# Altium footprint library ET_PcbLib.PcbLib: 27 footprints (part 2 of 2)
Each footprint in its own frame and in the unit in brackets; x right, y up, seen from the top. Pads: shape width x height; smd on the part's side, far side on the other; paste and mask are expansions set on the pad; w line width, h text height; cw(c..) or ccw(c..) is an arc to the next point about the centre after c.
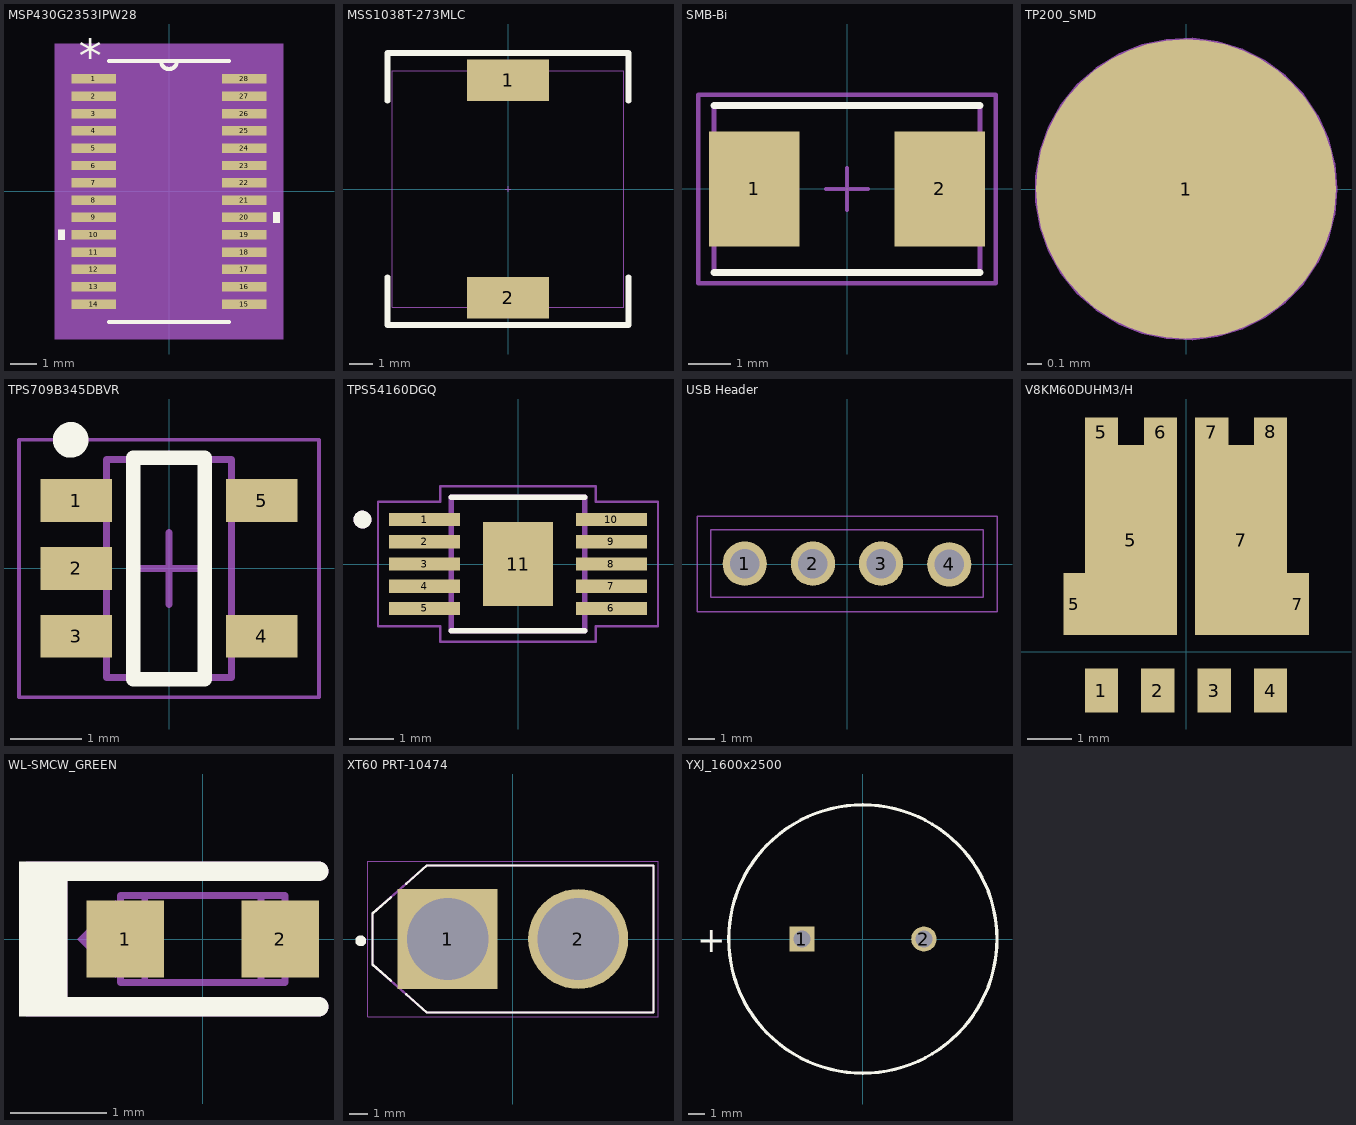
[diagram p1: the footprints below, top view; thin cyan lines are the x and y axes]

## MSP430G2353IPW28 [mil]
pads (28):
  rect 66x14 smd: 1(-111,166.34) 2(-111,140.75) 3(-111,115.16) 4(-111,89.57) 5(-111,63.98) 6(-111,38.39) 7(-111,12.8) 8(-111,-12.8) 9(-111,-38.39) 10(-111,-63.98) 11(-111,-89.57) 12(-111,-115.16) 13(-111,-140.75) 14(-111,-166.34) 15(111,-166.34) 16(111,-140.75) 17(111,-115.16) 18(111,-89.57) 19(111,-63.98) 20(111,-38.39) 21(111,-12.8) 22(111,12.8) 23(111,38.39) 24(111,63.98) 25(111,89.57) 26(111,115.16) 27(111,140.75) 28(111,166.34)
Top Overlay:
  region: -154,-56.48 -164,-56.48 -164,-71.48 -154,-71.48
  region: 154,-30.89 164,-30.89 164,-45.89 154,-45.89
  lines w6: -88.5,-193 88.5,-193 ; -88.5,193 88.5,193 ; -12,193 ccw(c0,193) 12,193
  text "*" at -133.5,175.34 h50
Mechanical 5:
  region: 169,-218 -169,-218 -169,218 169,218
Mechanical 13:
  lines w0: -12,193 ccw(c0,193) 12,193
  lines w1: -130,-172.34 -130,-160.34 -88.5,-160.34 -88.5,-172.34 -130,-172.34 ; -130,-146.75 -130,-134.75 -88.5,-134.75 -88.5,-146.75 -130,-146.75 ; -130,-121.16 -130,-109.16 -88.5,-109.16 -88.5,-121.16 -130,-121.16 ; -130,-95.57 -130,-83.57 -88.5,-83.57 -88.5,-95.57 -130,-95.57 ; -130,-69.98 -130,-57.98 -88.5,-57.98 -88.5,-69.98 -130,-69.98 ; -130,-44.39 -130,-32.39 -88.5,-32.39 -88.5,-44.39 -130,-44.39 ; -130,-18.8 -130,-6.8 -88.5,-6.8 -88.5,-18.8 -130,-18.8 ; -130,6.8 -130,18.8 -88.5,18.8 -88.5,6.8 -130,6.8 ; -130,32.39 -130,44.39 -88.5,44.39 -88.5,32.39 -130,32.39 ; -130,57.98 -130,69.98 -88.5,69.98 -88.5,57.98 -130,57.98 ; -130,83.57 -130,95.57 -88.5,95.57 -88.5,83.57 -130,83.57 ; -130,109.16 -130,121.16 -88.5,121.16 -88.5,109.16 -130,109.16 ; -130,134.75 -130,146.75 -88.5,146.75 -88.5,134.75 -130,134.75 ; -130,160.34 -130,172.34 -88.5,172.34 -88.5,160.34 -130,160.34 ; -88.5,-193 88.5,-193 88.5,193 -88.5,193 -88.5,-193 ; 88.5,-172.34 88.5,-160.34 130,-160.34 130,-172.34 88.5,-172.34 ; 88.5,-146.75 88.5,-134.75 130,-134.75 130,-146.75 88.5,-146.75 ; 88.5,-121.16 88.5,-109.16 130,-109.16 130,-121.16 88.5,-121.16 ; 88.5,-95.57 88.5,-83.57 130,-83.57 130,-95.57 88.5,-95.57 ; 88.5,-69.98 88.5,-57.98 130,-57.98 130,-69.98 88.5,-69.98 ; 88.5,-44.39 88.5,-32.39 130,-32.39 130,-44.39 88.5,-44.39 ; 88.5,-18.8 88.5,-6.8 130,-6.8 130,-18.8 88.5,-18.8 ; 88.5,6.8 88.5,18.8 130,18.8 130,6.8 88.5,6.8 ; 88.5,32.39 88.5,44.39 130,44.39 130,32.39 88.5,32.39 ; 88.5,57.98 88.5,69.98 130,69.98 130,57.98 88.5,57.98 ; 88.5,83.57 88.5,95.57 130,95.57 130,83.57 88.5,83.57 ; 88.5,109.16 88.5,121.16 130,121.16 130,109.16 88.5,109.16 ; 88.5,134.75 88.5,146.75 130,146.75 130,134.75 88.5,134.75 ; 88.5,160.34 88.5,172.34 130,172.34 130,160.34 88.5,160.34
  text "*" at -133.5,175.34 h50
Mechanical 15:
  region: 154,-203 -154,-203 -154,203 154,203
  lines w6: -154,-203 -154,203 154,203 154,-203 -154,-203
3D body "MSP430G2353IPW28.step": height 47.09, standoff 0, extent -129.99,-192.99 130.01,193
3D body: height 10, standoff 0, extent 0,0 10,10

## MSS1038T-273MLC [mil] "Coilcraft Shielded Power Inductors"
height 150
pads (2):
  rect 140x70 smd: 1(0,185) 2(0,-185)
Top Overlay:
  lines w10: -205,-150 -205,-231.5 205,-231.5 205,-150 ; -205,150 -205,231.5 205,231.5 205,150
Mechanical 13:
  lines w1: -5,0 5,0 ; 0,-5 0,5
Mechanical 14:
  lines w1: -197,-201 197,-201 197,201 -197,201 -197,-201
3D body "MSS1038.STEP": height 157.54, standoff 0.06, extent -200.79,-202.76 200.78,202.75

## SMB-Bi [mm] "Molded Diode, 2-Leads, Body 5.4x3.6mm, IPC Medium Density, based on OnSemi component dimensions"
height 2.65
pads (2):
  rect 2.159x2.743 smd: 1(-2.21,0) 2(2.21,0)
Top Overlay:
  lines w0.178: -3.175,-1.994 3.175,-1.994 ; -3.175,1.994 3.175,1.994
Mechanical 5:
  lines w0.127: -3.175,-1.994 3.175,-1.994 3.175,-1.765 3.175,1.765 3.175,1.994 -3.175,1.994 -3.175,1.765 -3.175,-1.765 -3.175,-1.994
  text ".Designator" at -2.311,-0.508 h1.02
Mechanical 15:
  lines w0.1: -0.5,0 0.5,0 ; 0,-0.5 0,0.5 ; -3.55,-2.25 -3.55,2.25 3.55,2.25 3.55,-2.25 -3.55,-2.25
3D body "SMB-Bi.stp": height 2.26, standoff 0.01, extent -2.65,-1.85 2.65,1.85

## TP200_SMD [mm] "Test Point, Single Side Land,2.00mm Land SMD"
pads (1):
  round 2.1 smd paste-10 mask-0.1: 1(0,0)
Mechanical 7:
  circle w0.02: c0,0 r1.05
Mechanical 9:
  lines w0.02: -0.5,0 0.5,0 ; 0,-0.5 0,0.5
Mechanical 11:
  text ".Designator" at -0.85,-0.15 h0.8
3D body: height 0.02, standoff 0, extent -0.992,-0.998 1,0.998

## TPS709B345DBVR [mm] "SOT23, 5-Leads, Body 2.90x2.80mm, Pitch 0.95mm, IPC Medium Density"
height 1.45
pads (5):
  rect 1x0.6 smd: 1(-1.3,0.95) 2(-1.3,0) 3(-1.3,-0.95) 4(1.3,-0.95) 5(1.3,0.95)
Top Overlay:
  circle w0.25: c-1.375,1.8 r0.125
  lines w0.2: -0.5,-1.55 -0.5,1.55 0.5,1.55 0.5,-1.55 -0.5,-1.55
Top Assembly:
  lines w0.1: -0.875,-1.525 0.875,-1.525 0.875,1.525 -0.875,1.525 -0.875,-1.525
Top Courtyard:
  lines w0.05: -2.1,-1.8 2.1,-1.8 2.1,1.8 -2.1,1.8 -2.1,-1.8
  lines w0.1: -0.5,0 0.5,0 ; 0,-0.5 0,0.5
Mechanical 11:
  text ".Designator" at -0.5,1.5 h1.5
3D body "SOT95P280X145-5N.step": height 1.45, standoff 0, extent -1.5,-1.525 1.5,1.525

## TPS54160DGQ [mm]
pads (11):
  rect 1.6x0.3 smd paste-2 mask+0: 1(-2.1,1) 2(-2.1,0.5) 3(-2.1,0) 4(-2.1,-0.5) 5(-2.1,-1) 6(2.1,-1) 7(2.1,-0.5) 8(2.1,0) 9(2.1,0.5) 10(2.1,1)
  rect 1.57x1.88 smd: 11(0,0)
Top Overlay:
  circle w0.2: c-3.5,1 r0.1
  lines w0.127: -1.5,-1.5 1.5,-1.5 ; -1.5,1.5 1.5,1.5
Top Paste:
  region: 2.875,0.875 1.325,0.875 1.325,1.125 2.875,1.125
  region: 2.875,0.375 1.325,0.375 1.325,0.625 2.875,0.625
  region: 2.875,-0.125 1.325,-0.125 1.325,0.125 2.875,0.125
  region: 2.875,-0.625 1.325,-0.625 1.325,-0.375 2.875,-0.375
  region: 2.875,-1.125 1.325,-1.125 1.325,-0.875 2.875,-0.875
  region: -1.325,-1.125 -2.875,-1.125 -2.875,-0.875 -1.325,-0.875
  region: -1.325,-0.625 -2.875,-0.625 -2.875,-0.375 -1.325,-0.375
  region: -1.325,-0.125 -2.875,-0.125 -2.875,0.125 -1.325,0.125
  region: -1.325,0.375 -2.875,0.375 -2.875,0.625 -1.325,0.625
  region: -1.325,0.875 -2.875,0.875 -2.875,1.125 -1.325,1.125
Top Solder:
  region: 2.95,0.8 1.25,0.8 1.25,1.2 2.95,1.2
  region: 2.95,0.3 1.25,0.3 1.25,0.7 2.95,0.7
  region: 2.95,-0.2 1.25,-0.2 1.25,0.2 2.95,0.2
  region: 2.95,-0.7 1.25,-0.7 1.25,-0.3 2.95,-0.3
  region: 2.95,-1.2 1.25,-1.2 1.25,-0.8 2.95,-0.8
  region: -1.25,-1.2 -2.95,-1.2 -2.95,-0.8 -1.25,-0.8
  region: -1.25,-0.7 -2.95,-0.7 -2.95,-0.3 -1.25,-0.3
  region: -1.25,-0.2 -2.95,-0.2 -2.95,0.2 -1.25,0.2
  region: -1.25,0.3 -2.95,0.3 -2.95,0.7 -1.25,0.7
  region: -1.25,0.8 -2.95,0.8 -2.95,1.2 -1.25,1.2
Mechanical 13:
  circle w0.2: c-3.5,1 r0.1
  lines w0.127: -1.5,-1.5 1.5,-1.5 1.5,1.5 -1.5,1.5 -1.5,-1.5
Mechanical 15:
  lines w0.05: -3.15,-1.4 -1.75,-1.4 -1.75,-1.75 1.75,-1.75 1.75,-1.4 3.15,-1.4 3.15,1.4 1.75,1.4 1.75,1.75 -1.75,1.75 -1.75,1.4 -3.15,1.4 -3.15,-1.4
3D body "step_temp.STEP": height 1.1, standoff 0, extent -2.45,-1.5 2.45,1.5

## USB Header [mil] "1x4 Header, Through Hole, Vertical"
height 336
pads (4):
  round 65 hole 43.3 mask+2.95: 1(-150,0.5) 2(-50,0.5) 3(50,0.5) 4(150.01,-0.5)
Mechanical 5:
  lines w1.97: -220,-70 220,-70 220,70 -220,70 -220,-70
Mechanical 7:
  lines w1.97: -199.99,-48.99 200,-48.99 200,50 -199.99,50 -199.99,-48.99
Mechanical 11:
  text ".Designator" at 230,30 h59.06
3D body "61300411121_Downlaod_STP_61300411121_rev1.stp": height 341.22, standoff -113.11, extent -200,-50 200,50

## V8KM60DUHM3/H [mm]
pads (12):
  rect 0.75x1 smd: 1(-1.905,-0.875) 2(-0.635,-0.875) 3(0.635,-0.875) 4(1.905,-0.875)
  rect 0.5x1.4 smd: 5(-2.514,1.073) 7(2.52,1.074)
  rect 0.75x0.65 smd: 5(-1.905,4.95) 6(-0.574,4.95) 7(0.577,4.95) 8(1.905,4.953)
  rect 2.08x4.28 smd: 5(-1.24,2.515) 7(1.24,2.515)

## WL-SMCW_GREEN [mm] "WURTH"
height 0.8
pads (2):
  rect 0.8x0.8 smd: 1(-0.8,0) 2(0.8,0)
Top Overlay:
  rectangle: -1.9,-0.8 -1.4,0.8
  lines w0.2: -1.6,-0.7 1.2,-0.7 ; -1.6,0.7 1.2,0.7
Mechanical 5:
  region: -0.9,-0.4 -0.9,0.4 -1.3,0
  lines w0.2: -1.65,-0.7 -1.65,0.55 ; 1.2,-0.7 -1.5,-0.7 ; 1.2,0.7 -1.5,0.7 ; -1.5,-0.7 -1.8,-0.7 -1.8,0.7 -1.5,0.7 ; -1.5,-0.7 -1.5,0.7
  text ".Designator" at -0.8,-0.3 h0.45
Mechanical 13:
  lines w0.07: -0.6,-0.45 -0.6,0.45 ; 0.6,-0.45 0.6,0.45 ; -0.85,-0.45 0.85,-0.45 0.85,0.45 -0.85,0.45 -0.85,-0.45
3D body: height 0.8, standoff 0.35, extent -0.599,-0.449 0.599,0.449
3D body: height 0.35, standoff 0, extent 0.601,-0.449 0.849,0.449
3D body: height 0.35, standoff 0, extent -0.599,-0.449 0.599,0.449
3D body: height 0.35, standoff 0, extent -0.849,-0.449 -0.601,0.449

## XT60 PRT-10474 [mm]
pads (2):
  rect 5.516x5.516 hole 4.5: 1(-3.6,0)
  round 5.516 hole 4.5: 2(3.6,0)
Top Overlay:
  circle w0.3: c-8.4,-0.1 r0.15
  lines w0.127: -6.73,-2.3 -7.75,-1.4 -7.75,1.4 -6.73,2.3 ; -5.88,-3.05 -4.75,-4.05 7.75,-4.05 7.75,4.05 -4.75,4.05 -5.88,3.05
Mechanical 13:
  lines w0.127: -7.75,-1.4 -4.75,-4.05 7.75,-4.05 7.75,4.05 -4.75,4.05 -7.75,1.4 -7.75,-1.4
Mechanical 15:
  lines w0.05: -8,-4.3 8,-4.3 8,4.3 -8,4.3 -8,-4.3

## YXJ_1600x2500 [mm] "TH, 2-Leads, Dia 16mm, Pin Spacing 7.5mm"
height 27
pads (2):
  rrect6% 1.55x1.55 hole 1.05: 1(-3.75,0)
  round 1.55 hole 1.05: 2(3.75,0)
Top Overlay:
  circle w0.2: c0,0 r8.25
  text "+" at -10.2,-0.8 h1.52
Mechanical 5:
  circle w0.1: c0,0 r8.25
  text "+" at -10.2,-0.8 h1.52
  text ".Designator" at -2,-0.7 h1.85
3D body "YXJ_1600x2500.stp": height 27.01, standoff -4, extent -8.25,-8.25 8.26,8.25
